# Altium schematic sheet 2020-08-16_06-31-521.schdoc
size 288 x 115 mm; SheetNumber: 1; SheetTotal: 1
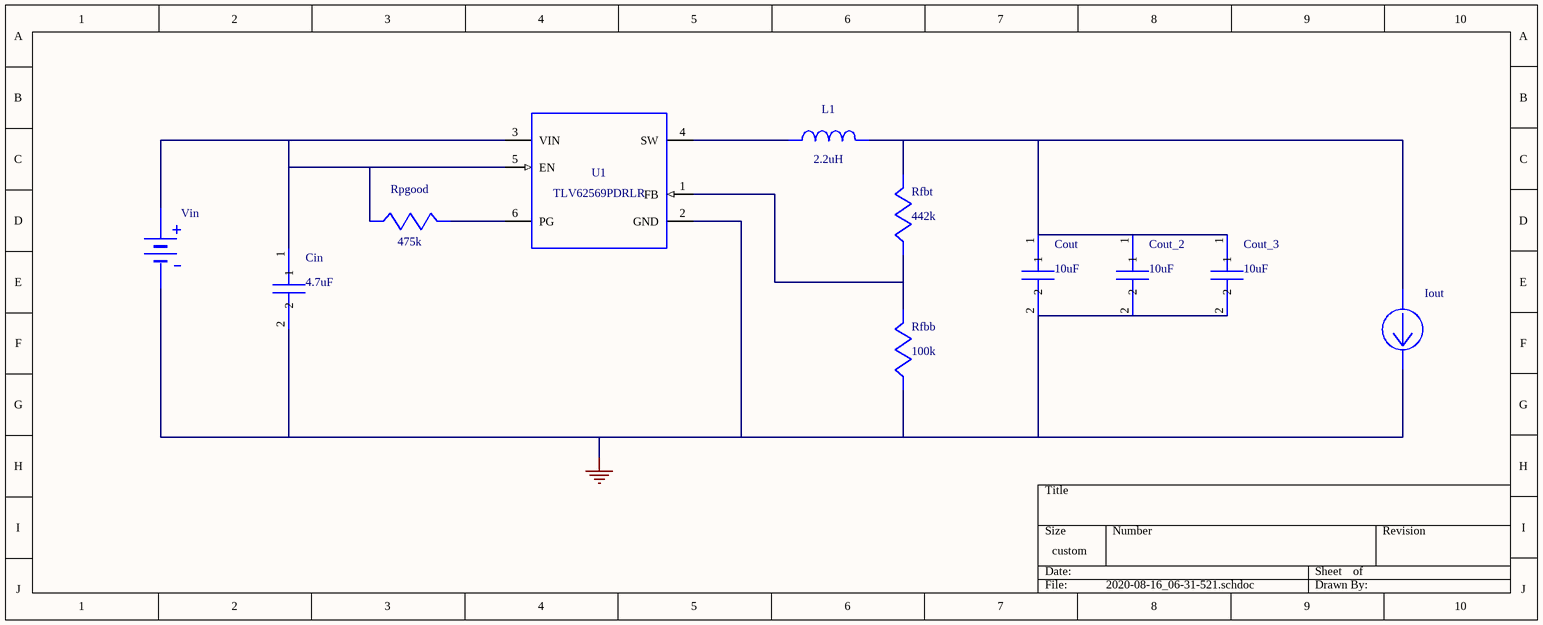
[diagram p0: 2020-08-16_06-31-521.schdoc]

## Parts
Cin  value 4.7uF  (hidden comment: GRM155R61A475MEAAD)
Cout  value 10uF  (hidden comment: GRJ155R60J106ME11D)
Cout_2  value 10uF  (hidden comment: GRJ155R60J106ME11D)
Cout_3  value 10uF  (hidden comment: GRJ155R60J106ME11D)
Iout  WB_CURRENT_LOAD  (value not drawn)
L1  value 2.2uH  (hidden comment: IHLP2020CZER2R2M11)
Rfbb  value 100k  (hidden comment: CRCW0402100KFKED)
Rfbt  value 442k  (hidden comment: RC0201FR-07442KL)
Rpgood  value 475k  (hidden comment: CRCW0402475KFKED)
U1  TLV62569PDRLR
Vin  WB_BATTERY  (value not drawn)

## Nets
0: Cin.2 Cout.2 Cout_2.2 Cout_3.2 Iout.2(-) Rfbb.2 U1.2(GND) Vin.2(-)
NetCin_1: Cin.1 Rpgood.2 U1.3(VIN) U1.5(EN) Vin.1(+)
NetCout_1: Cout.1 Cout_2.1 Cout_3.1 Iout.1(+) L1.2 Rfbt.1
NetL1_1: L1.1 U1.4(SW)
NetRfbb_1: Rfbb.1 Rfbt.2 U1.1(FB)
NetRpgood_1: Rpgood.1 U1.6(PG)

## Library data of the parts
Cin = GRM155R61A475MEAAD: GRM155R61A475MEA; Manufacturer Name: MuRata
Cout Cout_2 Cout_3 = GRJ155R60J106ME11D: GRJ155R60J106ME1; Manufacturer Name: MuRata
L1 = IHLP2020CZER2R2M11: Unknown; Manufacturer Name: Vishay-Dale
Rfbb = CRCW0402100KFKED: Manufacturer Name: Vishay-Dale
Rfbt = RC0201FR-07442KL: Manufacturer Name: Yageo
Rpgood = CRCW0402475KFKED: Manufacturer Name: Vishay-Dale
U1 = TLV62569PDRLR: Manufacturer Name: Texas Instruments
